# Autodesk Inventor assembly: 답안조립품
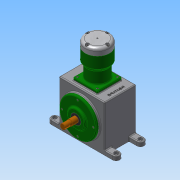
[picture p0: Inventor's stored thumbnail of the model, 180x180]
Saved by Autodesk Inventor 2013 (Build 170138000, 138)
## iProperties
Created: 2016-11
Part Number: 답안조립품
Document SubType Name: Assembly
Designer: Administrator
Author: Administrator
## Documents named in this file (16)
- C:\Users\Administrator\Desktop\361108V1012\답안조립품.iam
- C:\Users\Administrator\Desktop\361108V1012\본체.ipt
- C:\Users\Administrator\Desktop\361108V1012\베어링 20 x 47 x 14.ipt
- C:\Users\Administrator\Desktop\361108V1012\메인크랭크축.ipt
- C:\Users\Administrator\Desktop\361108V1012\베어링 NA 4902.ipt
- C:\Users\Administrator\Desktop\361108V1012\크랭크보조축.ipt
- C:\Users\Administrator\Desktop\361108V1012\앞커버.ipt
- C:\Users\Administrator\Desktop\361108V1012\오일 실 20 35 8.ipt
- C:\Users\Administrator\Desktop\361108V1012\실린더.ipt
- C:\Users\Administrator\Desktop\361108V1012\피스톤.ipt
- C:\Users\Administrator\Desktop\361108V1012\커넥팅로드.ipt
- C:\Users\Administrator\Desktop\361108V1012\피스톤핀.ipt
- C:\Users\Administrator\Desktop\361108V1012\실린더헤드.ipt
- C:\Users\Administrator\Desktop\361108V1012\볼트 M4 x 8.ipt
- C:\Users\Administrator\Desktop\361108V1012\볼트 M5 x 20.ipt
- C:\Users\Administrator\Desktop\361108V1012\가변스프링.ipt
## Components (15 placed, 5 different names)
1. 피스톤:1
2. 피스톤핀:1
3. 가변스프링:1
4. ISO 4762 M4 x 8:5
5. ISO 4762 M4 x 8:6
6. ISO 4762 M4 x 8:7
7. ISO 4762 M4 x 8:8
8. ISO 4762 M4 x 8:1
9. ISO 4762 M4 x 8:2
10. ISO 4762 M4 x 8:3
11. ISO 4762 M4 x 8:4
12. ISO 4762 M5 x 20:1
13. ISO 4762 M5 x 20:2
14. ISO 4762 M5 x 20:3
15. ISO 4762 M5 x 20:4
